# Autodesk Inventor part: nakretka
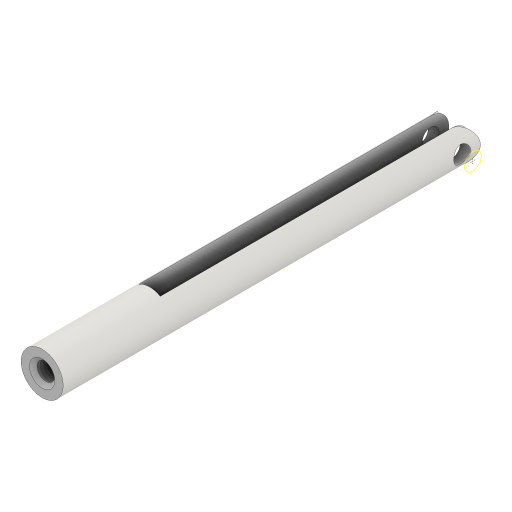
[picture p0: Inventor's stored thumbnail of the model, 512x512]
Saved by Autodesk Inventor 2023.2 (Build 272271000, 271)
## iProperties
Created: 2022-12
Part Number: nakretka
Material: Ogólny
Document SubType Name: Modeling
Designer: DOM
Density: 1 g/cm^3
Appearance: Domyślna
Mass: 30.7162 g
Surface Area: 162.37 cm^2
Volume: 30.7162 cm^3
Author: DOM
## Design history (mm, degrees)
sketch "Szkic1"
  geometry: C1 r 10 at (0, 0); 1 further point
  constraints: 1 centre point, 1 coincident
  dimensions: "d0" = 20 diameter of C1
extrude "Wyciągnięcie proste1" new body sketch "Szkic1" stored distance "d1" = 200; taper "d2" = 0 deg
sketch "Szkic2"
  geometry: L1 (5, 48.769)-(-5, 48.769); L2 (-5, 48.769)-(-5, -101.231); L3 (-5, -101.231)-(5, -101.231); L4 (5, -101.231)-(5, 48.769); L5 (5, 48.769)-(-5, -101.231); L6 (-5, 48.769)-(5, -101.231); 2 further points
  constraints: 12 end point, 2 midpoint, 2 parallel, 1 horizontal, 1 perpendicular
  dimensions: "d3" = 10 distance of L3.end L2.end; "d4" = 150 distance of L2.end L1.end
extrude "Wyciągnięcie proste2" cut sketch "Szkic2" stored distance "d5" = 200; taper "d6" = 0 deg
sketch "Szkic3"
  geometry: L1 (8.66, -100)-(-8.66, -100) reference; C1 r 4 at (0, -90); 2 further points
  constraints: 1 centre point, 1 midpoint
  dimensions: "d7" = 8 diameter of C1; "d8" = 10 distance of point (0, -100) C1.centre
extrude "Wyciągnięcie proste3" cut sketch "Szkic3" stored distance "d9" = 200; taper "d10" = 0 deg
sketch "Szkic4"
  geometry: C1 r 10 at (0, 0) reference; 2 further points
  constraints: 1 coincident
hole "Otwór1" sketch "Szkic4" at (0, 0) diameter "d11" = 8.376; stored, may be unused: countersink angle "d15" = 90 deg, drill point angle "d17" = 118 deg; dims "d12" = 20, "d13" = 12, "d14" = 2, "d16" = 8
sketch "Szkic5"
  geometry: L1 (8.66, -100)-(8.66, 48.769) reference; L2 (8.66, 48.769)-(8.66, -100) reference; L3 (-8.66, -100)-(-8.66, 48.769) reference; L4 (8.66, -100)-(-8.66, -100) reference; C1 r 4 at (0, -90) reference; A1 r 8.66 centre (0, -90) between (-8.66, -90) and (8.66, -90); 2 further points
  constraints: 2 point on circle, 2 point on line, 1 centre point, 1 coincident, 1 tangent
extrude "Wyciągnięcie proste4" cut sketch "Szkic5" extent not by distance; stored distance "d18" = 0; taper "d19" = 0 deg
node "Płaszczyzna konstrukcyjna1"
sketch "Szkic7"
  geometry: 4 further points
  constraints: 1 coincident, 1 horizontal alignment
node "Bryła1"
other parameters: "d20" = 15
